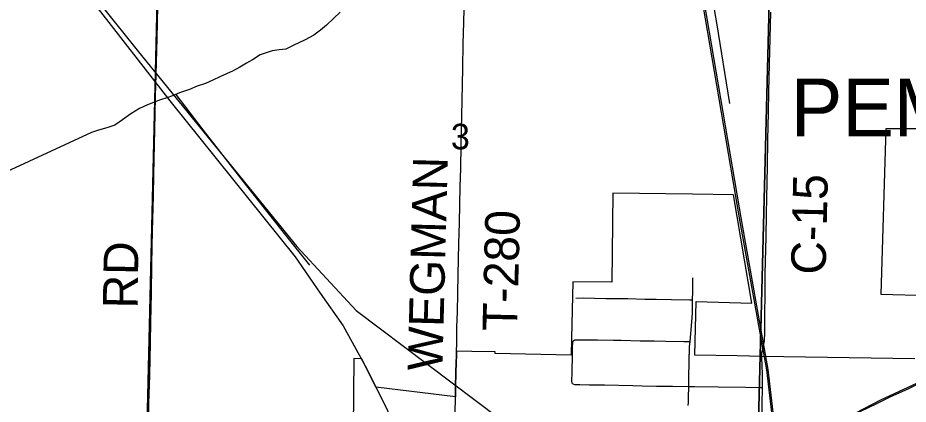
# Model space of a CAD drawing. Extents: x 0 to 34, y 0 to 22.
# Drawn here: x 4.218 to 5.678, y 15.1 to 15.733 of the extents above; entities that cross this region are included whole.
import ezdxf

# ---------------------------------------------------------------- set-up
doc = ezdxf.new("R2010")
doc.units = 0
for name, color, linetype in [('GM_X_City_Street', 7, 'Continuous'), ('GM_X_Corporation_Text', 7, 'Continuous'), ('GM_X_County_Road', 7, 'Continuous'), ('GM_X_County_Road_Text', 7, 'Continuous'), ('GM_X_Minor_River', 7, 'Continuous'), ('GM_X_Rail_Line', 7, 'Continuous'), ('GM_X_Section', 7, 'Continuous'), ('GM_X_Section_Text', 7, 'Continuous'), ('GM_X_State_Route', 7, 'Continuous'), ('GM_X_Township_Road', 7, 'Continuous'), ('GM_X_Township_Road_Text', 7, 'Continuous')]:
    doc.layers.add(name, color=color, linetype=linetype)

msp = doc.modelspace()

# ---------------------------------------------------------------- linework, layer by layer
at = {"layer": 'GM_X_City_Street'}
for points in [[(5.3175, 15.0976), (5.3176, 15.1025), (5.3177, 15.1102), (5.3181, 15.1285), (5.3182, 15.1304), (5.3184, 15.1491), (5.3187, 15.1631), (5.3191, 15.1804), (5.3192, 15.1818), (5.3197, 15.1942), (5.3203, 15.2021), (5.3234, 15.2345), (5.3243, 15.2486), (5.3242, 15.2579), (5.3244, 15.2707), (5.3247, 15.2844), (5.3248, 15.2906), (5.325, 15.3065)], [(5.1332, 15.2733), (5.1449, 15.2736), (5.1823, 15.273), (5.2181, 15.2725), (5.2461, 15.2719), (5.2648, 15.2716), (5.2897, 15.271), (5.3193, 15.2708), (5.3244, 15.2707)], [(5.1283, 15.1331), (5.127, 15.1346), (5.1265, 15.1365), (5.1268, 15.1521), (5.1273, 15.1797), (5.1276, 15.188), (5.1276, 15.194), (5.1279, 15.1998), (5.1286, 15.2027), (5.1296, 15.204)], [(5.1296, 15.204), (5.1313, 15.2049), (5.134, 15.2051), (5.145, 15.2048), (5.1684, 15.2048), (5.1949, 15.2043), (5.2073, 15.2042), (5.2383, 15.2034), (5.2496, 15.2033), (5.2617, 15.2032), (5.2804, 15.2029), (5.3099, 15.2025), (5.3146, 15.2023), (5.3203, 15.2021)], [(5.1283, 15.1331), (5.131, 15.132), (5.1338, 15.1317), (5.1394, 15.1316), (5.1549, 15.1314), (5.1798, 15.131), (5.2264, 15.13), (5.242, 15.1298), (5.2653, 15.1293), (5.2917, 15.1291), (5.3181, 15.1285), (5.3277, 15.1283), (5.3665, 15.1279), (5.4116, 15.1274), (5.434, 15.127), (5.4394, 15.1269)]]:
    msp.add_lwpolyline(points, dxfattribs=at)
at = {"layer": 'GM_X_County_Road'}
for points in [[(5.438, 15.1772), (5.438, 15.1806), (5.4383, 15.1843), (5.44, 15.1918), (5.4422, 15.2034), (5.4426, 15.208), (5.443, 15.2122), (5.4432, 15.2184), (5.4429, 15.2511), (5.4433, 15.276), (5.4437, 15.3133), (5.4449, 15.374), (5.4457, 15.4113), (5.4462, 15.4377), (5.4474, 15.4891), (5.4479, 15.5326), (5.449, 15.5777), (5.4496, 15.6119), (5.4507, 15.657), (5.4529, 15.7422)], [(5.4394, 15.1269), (5.4394, 15.1393), (5.4391, 15.1501), (5.4388, 15.1615), (5.438, 15.1772)], [(5.4374, 15.0448), (5.438, 15.0605), (5.4385, 15.0868), (5.4388, 15.1038), (5.4393, 15.1223), (5.4394, 15.1269)]]:
    msp.add_lwpolyline(points, dxfattribs=at)
at = {"layer": 'GM_X_Minor_River'}
for points in [[(5.3241, 15.946), (5.3437, 15.8402), (5.3635, 15.7247), (5.3849, 15.5925)], [(4.7463, 15.7423), (4.7354, 15.7316), (4.7242, 15.7208), (4.7145, 15.7127), (4.7033, 15.7043), (4.6891, 15.6966), (4.6692, 15.6872), (4.6577, 15.6815), (4.6463, 15.6806), (4.6349, 15.6786), (4.625, 15.6754), (4.6154, 15.6719), (4.6027, 15.6642), (4.5928, 15.6584), (4.582, 15.6518), (4.5709, 15.646), (4.5494, 15.6359), (4.5375, 15.6309), (4.5257, 15.6254), (4.5119, 15.6208), (4.4993, 15.6155), (4.4829, 15.6098), (4.4718, 15.6051), (4.4622, 15.6016), (4.4519, 15.5984), (4.4404, 15.5941), (4.4305, 15.5902), (4.4175, 15.584), (4.4032, 15.5757), (4.3894, 15.5657), (4.377, 15.5566), (4.3641, 15.5527), (4.3503, 15.5485), (4.3385, 15.5446), (4.0301, 15.4025)], [(4.4771, 15.6073), (4.5211, 15.5493), (4.5868, 15.4653), (4.657, 15.3763), (4.6963, 15.3272)]]:
    msp.add_lwpolyline(points, dxfattribs=at)
at = {"layer": 'GM_X_Rail_Line'}
for points in [[(5.5292, 14.4768), (5.5206, 14.546), (5.4959, 14.7503), (5.4725, 14.9371), (5.462, 15.0205), (5.4461, 15.156), (5.4028, 15.3982), (5.2961, 16.0228), (5.1204, 17.0387), (4.9909, 17.7947), (4.7368, 19.2661), (4.6073, 20.0278), (4.4575, 20.9)], [(5.5755, 14.1), (5.542, 14.3915), (5.5241, 14.5438), (5.4984, 14.7506), (5.475, 14.9374), (5.4645, 15.0208), (5.4485, 15.1564), (5.4052, 15.3987), (5.2986, 16.0233), (5.1228, 17.0391), (4.9933, 17.7951), (4.7392, 19.2665), (4.6097, 20.0282), (4.4576, 20.9)], [(4.2319, 16.1435), (4.2654, 15.9524), (4.2832, 15.8753), (4.3076, 15.816), (4.3421, 15.7575), (4.467, 15.5965), (4.6728, 15.341), (4.7136, 15.2817), (4.7513, 15.2282), (4.7901, 15.1572), (4.824, 15.0894), (4.8579, 14.9796), (4.8789, 14.8794), (4.8951, 14.7809), (4.9067, 14.6373)], [(4.2385, 16.1435), (4.2773, 15.9412), (4.2937, 15.874), (4.3201, 15.8186), (4.3563, 15.7514), (4.4159, 15.6771), (4.6754, 15.3582), (4.7729, 15.2528), (5.0077, 15.0761), (5.1902, 14.9484), (5.254, 14.8846)], [(5.4683, 15.0207), (5.6332, 15.1067), (5.7819, 15.1753), (6.2027, 15.4338), (6.5076, 15.6796), (6.6489, 15.6828), (6.8134, 15.745), (7.4742, 16.0534)]]:
    msp.add_lwpolyline(points, dxfattribs=at)
at = {"layer": 'GM_X_Section'}
for points in [[(3.4754, 16.0365), (4.4532, 16.0374), (4.4299, 15.0671), (3.4378, 15.0391), (3.4686, 16.0366)], [(4.4786, 16.0375), (5.457, 16.0346), (5.4321, 15.051), (4.9949, 15.0647), (4.4299, 15.0671), (4.4532, 16.0374)], [(5.476, 16.0344), (6.437, 16.0283), (6.4232, 15.0563), (5.4321, 15.051), (5.457, 16.0346)]]:
    msp.add_lwpolyline(points, close=True, dxfattribs=at)
at = {"layer": 'GM_X_State_Route'}
msp.add_lwpolyline([(5.5151, 15.0465), (5.5212, 15.0496), (5.5602, 15.0689), (5.5853, 15.0812), (5.6106, 15.0931), (5.6302, 15.1025), (5.6498, 15.112), (5.678, 15.1249), (5.6934, 15.1321)], dxfattribs=at)
at = {"layer": 'GM_X_Township_Road'}
for points in [[(4.432, 15.0602), (4.4321, 15.066), (4.4329, 15.1008), (4.4342, 15.1468), (4.4353, 15.2002), (4.436, 15.2344), (4.437, 15.2817), (4.4376, 15.3277), (4.4383, 15.3581), (4.439, 15.3836), (4.4402, 15.4408), (4.441, 15.4762), (4.4431, 15.575), (4.4438, 15.6043), (4.445, 15.6397), (4.4463, 15.6993), (4.4473, 15.7515), (4.4483, 15.8174), (4.45, 15.8989), (4.4506, 15.9281), (4.4518, 15.9803), (4.4523, 16.0151), (4.4524, 16.0253)], [(4.9374, 15.1861), (4.9376, 15.1996), (4.9381, 15.226), (4.9389, 15.2509), (4.9403, 15.3115), (4.9414, 15.3628), (4.9422, 15.397), (4.9435, 15.4561), (4.9442, 15.4856), (4.9448, 15.5245), (4.9464, 15.5975), (4.9475, 15.6504), (4.9484, 15.6908), (4.9493, 15.725), (4.951, 15.7934), (4.9515, 15.8198), (4.952, 15.8385), (4.9529, 15.8633), (4.9542, 15.927), (4.955, 15.9597), (4.9565, 16.0063), (4.9568, 16.0156), (4.9572, 16.0239)], [(5.7311, 15.551), (5.6413, 15.5508), (5.633, 15.28), (5.7126, 15.2774)], [(5.6888, 15.1736), (5.4378, 15.1778), (5.3978, 15.1785), (5.3284, 15.1801), (5.3301, 15.268), (5.4219, 15.2651), (5.3914, 15.4426), (5.3241, 15.4438), (5.1936, 15.4456), (5.1918, 15.2994), (5.128, 15.3), (5.126, 15.2073), (5.1255, 15.1798), (5.0008, 15.1824), (5.0009, 15.1852), (4.9622, 15.1859), (4.9371, 15.1866), (4.9371, 15.1805), (4.9362, 15.1528), (4.9357, 15.1263), (4.9356, 15.1116), (4.8053, 15.1272), (4.7821, 15.1741), (4.7692, 15.1743), (4.7676, 15.0597)], [(4.9358, 15.1111), (4.9359, 15.1257), (4.9364, 15.1523), (4.9373, 15.18), (4.9374, 15.1861)], [(4.9346, 15.0543), (4.935, 15.0592), (4.9351, 15.0655), (4.9352, 15.0752), (4.9354, 15.0921), (4.9356, 15.1032), (4.9358, 15.1111)]]:
    msp.add_lwpolyline(points, dxfattribs=at)

# ---------------------------------------------------------------- texts
at = {"layer": 'GM_X_Corporation_Text'}
msp.add_text('PEMBERVILLE', height=0.094697, rotation=0, dxfattribs=at).set_placement((5.4856, 15.5386))
at = {"layer": 'GM_X_County_Road_Text'}
msp.add_text('C-15', height=0.05682, rotation=88.6573, dxfattribs=at).set_placement((5.5426, 15.3114))
at = {"layer": 'GM_X_Section_Text'}
msp.add_text('3', height=0.0419, rotation=0, dxfattribs=at).set_placement((4.9281, 15.5173))
at = {"layer": 'GM_X_Township_Road_Text'}
for s, rotation, p in [('WEGMAN', 88.5149, (4.9141, 15.154)), ('T-280', 88.5959, (5.0367, 15.2186)), ('RD', 89.0116, (4.4141, 15.2561))]:
    msp.add_text(s, height=0.05682, rotation=rotation, dxfattribs=at).set_placement(p)

doc.saveas('drawing.dxf')
